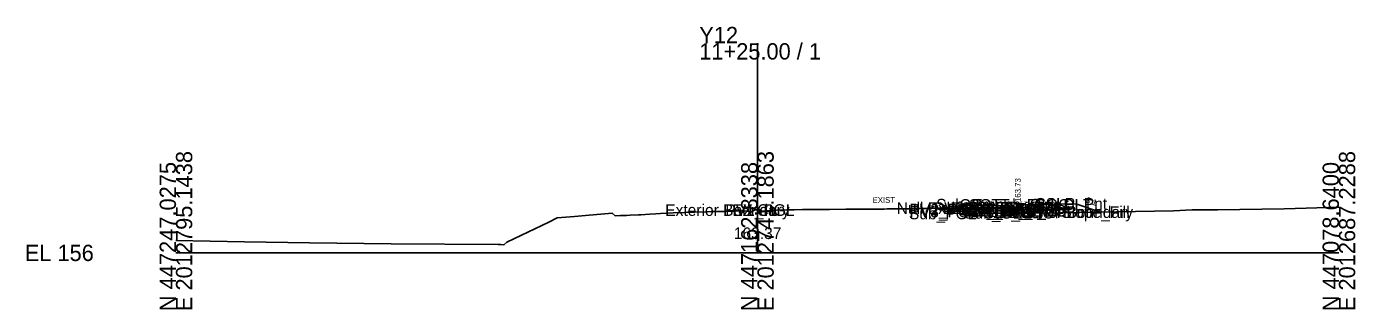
# Model space of a CAD drawing. Extents: x -26 to 1203, y -10 to 9542.
# Drawn here: x -25.7 to 202.8, y 2490.3 to 2538.8 of the extents above; entities that cross this region are included whole.
import ezdxf

# ---------------------------------------------------------------- set-up
doc = ezdxf.new("R2010")
doc.units = 0
for name, color, linetype in [('Default', 7, 'Continuous'), ('Exist Cross Section Cell', 7, 'Continuous'), ('Exist XS Center Line Elevation Label', 7, 'Continuous'), ('Exist XS Ground Line', 7, 'Continuous'), ('Prop CMT Conc Surface', 7, 'Continuous'), ('Prop CMT Concrete Structures', 7, 'Continuous'), ('Prop CMT Pvmt Course 1', 7, 'Continuous'), ('Prop CMT Pvmt Course 1 CG', 7, 'Continuous'), ('Prop CMT Pvmt Course 2', 7, 'Continuous'), ('Prop CMT Pvmt Course 3', 7, 'Continuous'), ('Prop CMT Pvmt Surface', 7, 'Continuous'), ('Prop CMT Slope Grass', 7, 'Continuous'), ('Prop CMT Subgrade Earthwork', 7, 'Continuous'), ('Prop XS Earthwork Shape', 7, 'Continuous'), ('Prop XS Hydro Elevations', 7, 'Continuous'), ('Prop XS SE Text', 7, 'Continuous'), ('Prop XS Side Slope Text', 7, 'Continuous'), ('Scratch_Level_0', 7, 'Continuous')]:
    doc.layers.add(name, color=color, linetype=linetype)

msp = doc.modelspace()

# ---------------------------------------------------------------- linework, layer by layer
at = {"layer": 'Exist Cross Section Cell'}
for p, q in [((100, 2500), (100, 2535.99)), ((0, 2500), (100, 2500)), ((100, 2500), (200, 2500))]:
    msp.add_line(p, q, dxfattribs=at)
at = {"layer": 'Exist XS Ground Line'}
msp.add_lwpolyline([(0, 2502.15), (11.77, 2501.9), (22.96, 2501.7), (37.02, 2501.57), (55.41, 2501.46), (55.89, 2501.42), (56.41, 2501.36), (56.91, 2501.86), (64.1, 2505.27), (65.53, 2506), (68.54, 2506.26), (70.45, 2506.42), (75.04, 2506.83), (75.54, 2506.36), (76.44, 2506.39), (77.48, 2506.43), (78.11, 2506.46), (79.56, 2506.54), (79.94, 2506.56), (81.52, 2506.64), (82.54, 2506.7), (83.34, 2506.74), (84.57, 2506.8), (85.5, 2506.85), (87.44, 2506.94), (87.95, 2506.97), (88.47, 2506.98), (89.19, 2507), (91.38, 2507.06), (92.33, 2507.08), (93.82, 2507.12), (94.36, 2507.13), (95.95, 2507.17), (97.33, 2507.22), (97.75, 2507.23), (99, 2507.07), (99.6, 2507.37), (100, 2507.37), (100.4, 2507.37), (101, 2507.07), (101.3, 2507.15), (103.3, 2507.35), (105.05, 2507.38), (106.29, 2507.4), (107.75, 2507.43), (109.26, 2507.45), (111.43, 2507.45), (112.37, 2507.45), (115.18, 2507.48), (116.98, 2507.49), (118.13, 2507.49), (120.19, 2507.51), (121.3, 2507.52), (121.78, 2507.53), (122.31, 2507.54), (124.07, 2507.56), (124.92, 2507.57), (126.24, 2507.59), (127.03, 2507.6), (128.53, 2507.61), (130.01, 2507.63), (130.72, 2507.65), (131.95, 2507.69), (132.25, 2507.68), (132.85, 2507.69), (134.18, 2507.73), (134.82, 2508.21), (139.26, 2508.18), (140.28, 2508.17), (140.79, 2508.17), (141.28, 2508.1), (144.17, 2507.66), (149.4, 2506.83), (151.93, 2506.89), (171.58, 2507.22), (174.75, 2507.38), (179.11, 2507.38), (190.61, 2507.58), (200, 2507.83)], dxfattribs=at)
at = {"layer": 'Prop CMT Conc Surface'}
msp.add_lwpolyline([(142.78, 2507.79), (144.78, 2507.73), (144.78, 2508.23), (145.28, 2508.23)], dxfattribs=at)
at = {"layer": 'Prop CMT Concrete Structures'}
for points in [[(142.78, 2507.79), (144.78, 2507.73), (144.78, 2508.23), (145.28, 2508.23)], [(145.28, 2508.23), (145.28, 2507.23), (142.78, 2507.21)], [(142.78, 2507.21), (142.78, 2507.79)]]:
    msp.add_lwpolyline(points, dxfattribs=at)
at = {"layer": 'Prop CMT Pvmt Course 1'}
for points in [[(100, 2507.35), (100, 2507.35)], [(132.25, 2507.68), (142.78, 2507.79)], [(132.25, 2507.68), (132.25, 2507.68)], [(132.25, 2507.43), (132.25, 2507.68)], [(142.78, 2507.54), (132.25, 2507.43)], [(142.78, 2507.79), (142.78, 2507.54)]]:
    msp.add_lwpolyline(points, dxfattribs=at)
at = {"layer": 'Prop CMT Pvmt Course 1 CG'}
for points in [[(142.78, 2507.21), (145.78, 2507.24), (146.11, 2506.91)], [(142.78, 2506.87), (142.78, 2507.21)], [(146.11, 2506.91), (142.78, 2506.87)]]:
    msp.add_lwpolyline(points, dxfattribs=at)
at = {"layer": 'Prop CMT Pvmt Course 2'}
for points in [[(132.25, 2507.43), (142.78, 2507.54)], [(132.25, 2507.1), (132.25, 2507.43)], [(142.78, 2507.21), (132.25, 2507.1)], [(142.78, 2507.54), (142.78, 2507.21)]]:
    msp.add_lwpolyline(points, dxfattribs=at)
at = {"layer": 'Prop CMT Pvmt Course 3'}
for points in [[(132.25, 2507.1), (142.78, 2507.21)], [(132.25, 2506.77), (132.25, 2507.1)], [(142.78, 2507.21), (142.78, 2506.87)], [(142.78, 2506.87), (132.25, 2506.77)]]:
    msp.add_lwpolyline(points, dxfattribs=at)
at = {"layer": 'Prop CMT Pvmt Surface'}
msp.add_lwpolyline([(132.25, 2507.68), (142.78, 2507.79)], dxfattribs=at)
at = {"layer": 'Prop CMT Slope Grass'}
msp.add_lwpolyline([(145.28, 2508.23), (154.78, 2508.42), (159, 2507.01)], dxfattribs=at)
at = {"layer": 'Prop CMT Subgrade Earthwork'}
for points in [[(132.25, 2506.77), (132.25, 2507.68)], [(142.78, 2506.87), (146.11, 2506.91), (147.48, 2508.27)], [(132.25, 2506.77), (142.78, 2506.87)], [(142.78, 2506.87), (132.25, 2506.77)]]:
    msp.add_lwpolyline(points, dxfattribs=at)
at = {"layer": 'Prop XS Earthwork Shape'}
for points in [[(132.25, 2507.68), (142.78, 2507.79), (143.43, 2507.77), (141.28, 2508.1), (140.79, 2508.17), (140.28, 2508.17), (139.26, 2508.18), (134.82, 2508.21), (134.18, 2507.73), (132.85, 2507.69)], [(142.78, 2506.87), (146.11, 2506.91), (146.49, 2507.29), (145.28, 2507.48), (145.28, 2507.23), (142.78, 2507.21), (142.78, 2507.79), (132.25, 2507.68), (132.25, 2506.77)], [(144.17, 2507.66), (145.28, 2507.48), (145.28, 2507.23), (142.78, 2507.21), (142.78, 2507.79), (143.43, 2507.77)], [(154.78, 2508.42), (159, 2507.01), (151.93, 2506.89), (149.4, 2506.83), (146.49, 2507.29), (147.48, 2508.27)]]:
    msp.add_lwpolyline(points, close=True, dxfattribs=at)

# ---------------------------------------------------------------- texts
at = {"layer": 'Default'}
msp.add_text('-', height=0.0001, dxfattribs=at).set_placement((0, 2500))
at = {"layer": 'Exist Cross Section Cell'}
for s, p in [('Y12', (90, 2535.99)), ('11+25.00 / 1', (90, 2533.19)), ('EL 156', (-26, 2498.6))]:
    msp.add_text(s, height=2.8, dxfattribs=at).set_placement(p)
for s, p in [('E 2012795.1438', (2.8, 2490)), ('E 2012741.1863', (102.8, 2490)), ('E 2012687.2288', (202.8, 2490)), ('N 447247.0275', (0, 2490)), ('N 447162.8338', (100, 2490)), ('N 447078.6400', (200, 2490))]:
    msp.add_text(s, height=2.8, rotation=90, dxfattribs=at).set_placement(p)
at = {"layer": 'Exist XS Center Line Elevation Label'}
msp.add_text('163.37', height=2, dxfattribs=at).set_placement((95.94, 2502.37))
at = {"layer": 'Prop XS Hydro Elevations'}
msp.add_text('163.73', height=1, rotation=90, dxfattribs=at).set_placement((145.28, 2508.73))
at = {"layer": 'Prop XS SE Text'}
msp.add_text('EXIST', height=1, rotation=0.5816, dxfattribs=at).set_placement((119.81, 2508.56))
at = {"layer": 'Prop XS Side Slope Text'}
msp.add_text('3:1', height=1, rotation=341.565, dxfattribs=at).set_placement((156.4, 2508.67))
at = {"layer": 'Scratch_Level_0'}
for s, p in [('Sub_Trench_Out_DLT', (130.74, 2507.27)), ('CSLP_Pnt', (147.65, 2507.42)), ('Exterior Boundary', (84.14, 2506.35)), ('PV1_PGL', (94.47, 2506.35)), ('EX CL', (95.67, 2506.35)), ('Null Ex EOP', (123.95, 2506.68)), ('Sub_PGL', (126.06, 2505.77)), ('PV2_PGL', (126.15, 2506.43)), ('PV3_PGL', (126.15, 2506.1)), ('PV1', (130.33, 2506.68)), ('CG_Top_Face', (134.74, 2507.23)), ('CG1_Shelf_Out', (135.03, 2506.24)), ('CG_Bot_IE', (135.39, 2506.21)), ('Sub_OEOT', (135.55, 2505.87)), ('CG_Top_Gut', (135.71, 2506.73)), ('PV2_OEOT', (135.65, 2506.54)), ('PV3_OEOT', (135.65, 2506.21)), ('CG_Top_BOC', (136.26, 2507.23)), ('PV1_OEOT', (136.21, 2506.79)), ('CG_Bot_BOC', (136.29, 2506.23)), ('Sub_OEOP', (138.91, 2505.91)), ('Exterior Boundary', (143.19, 2506)), ('Slope_Fill', (152.26, 2506))]:
    msp.add_text(s, height=2, dxfattribs=at).set_placement(p)

doc.saveas('drawing.dxf')
